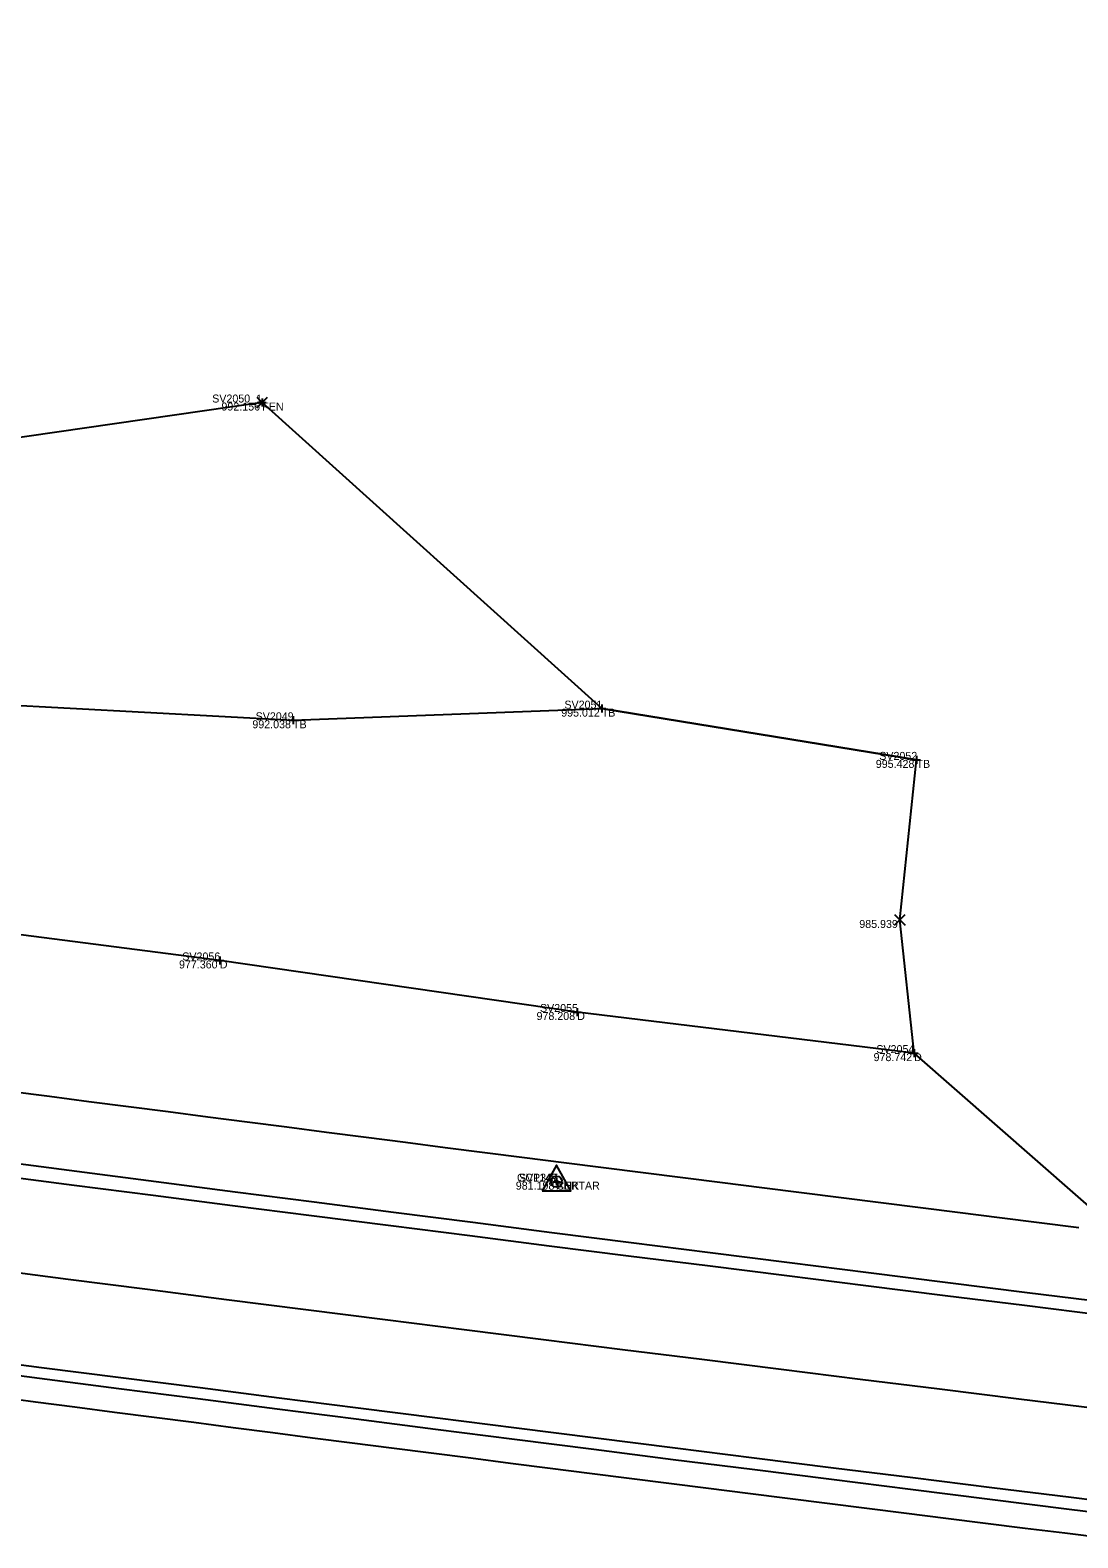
# Model space of a CAD drawing. Extents: x 2065431 to 2068157, y 709104 to 709719.
# Drawn here: x 2066723.6 to 2066854.9, y 709457.3 to 709646.1 of the extents above; entities that cross this region are included whole.
import ezdxf

# ---------------------------------------------------------------- set-up
doc = ezdxf.new("R2010")
doc.units = 0
for name, color, linetype in [('DT_X_Terrain_Boundary', 7, 'Continuous'), ('PM_X_Edge_Line', 7, 'Continuous'), ('PM_X_Lane_Line', 7, 'Continuous'), ('PV_X_EOP', 7, 'Continuous'), ('PV_X_Shoulder_Rumble_Strip', 7, 'Continuous'), ('RS_Raster1', 7, 'Continuous'), ('RW_X_CL_100_Bearings', 7, 'Continuous'), ('RW_X_Fee_WL', 7, 'Continuous'), ('SV_P_Aerial_Targets', 7, 'Continuous'), ('SV_X_Mon_Cells_Found', 7, 'Continuous'), ('SV_X_Text_Elevation', 7, 'Continuous'), ('SV_X_Text_Name', 7, 'Continuous'), ('SV_X_Top_of_Bank', 7, 'Continuous')]:
    doc.layers.add(name, color=color, linetype=linetype)

msp = doc.modelspace()

# ---------------------------------------------------------------- linework, layer by layer
at = {"layer": 'DT_X_Terrain_Boundary'}
msp.add_lwpolyline([(2066859.95, 709495.56), (2066834.34, 709517.99), (2066832.56, 709534.67), (2066834.65, 709554.72), (2066795.22, 709561.14), (2066752.69, 709599.48), (2066649.44, 709584.58), (2066543.44, 709596.37)], dxfattribs=at)
at = {"layer": 'PM_X_Edge_Line'}
for points in [[(2066719.2, 709502.76), (2066729.12, 709501.47), (2066739.04, 709500.2), (2066748.95, 709498.92), (2066758.87, 709497.66), (2066768.79, 709496.39), (2066778.71, 709495.13), (2066788.63, 709493.87), (2066798.56, 709492.62), (2066808.48, 709491.37), (2066818.4, 709490.13), (2066828.32, 709488.89), (2066838.25, 709487.65), (2066848.17, 709486.42), (2066858.09, 709485.19)], [(2066715.12, 709479.91), (2066725.04, 709478.63), (2066734.96, 709477.36), (2066744.9, 709476.09), (2066754.8, 709474.82), (2066764.72, 709473.56), (2066774.64, 709472.3), (2066784.56, 709471.04), (2066794.48, 709469.79), (2066804.4, 709468.54), (2066814.32, 709467.3), (2066824.25, 709466.06), (2066834.17, 709464.82), (2066844.09, 709463.59), (2066854.02, 709462.36), (2066863.94, 709461.13)]]:
    msp.add_lwpolyline(points, dxfattribs=at)
at = {"layer": 'PM_X_Lane_Line'}
msp.add_lwpolyline([(2066718.47, 709490.98), (2066728.39, 709489.68), (2066738.31, 709488.41), (2066748.23, 709487.15), (2066758.15, 709485.89), (2066768.07, 709484.63), (2066777.99, 709483.38), (2066787.91, 709482.13), (2066797.83, 709480.88), (2066807.76, 709479.64), (2066817.68, 709478.4), (2066827.6, 709477.16), (2066837.53, 709475.93), (2066847.45, 709474.7), (2066857.37, 709473.48)], dxfattribs=at)
at = {"layer": 'PV_X_EOP'}
for points in [[(2066721.07, 709513.24), (2066726.03, 709512.6), (2066730.98, 709511.95), (2066735.94, 709511.31), (2066740.9, 709510.67), (2066745.86, 709510.02), (2066750.82, 709509.38), (2066755.78, 709508.74), (2066760.74, 709508.1), (2066765.7, 709507.47), (2066770.65, 709506.83), (2066775.61, 709506.19), (2066780.57, 709505.56), (2066785.53, 709504.93), (2066790.49, 709504.29), (2066795.45, 709503.66), (2066800.41, 709503.03), (2066805.37, 709502.4), (2066810.33, 709501.78), (2066815.29, 709501.15), (2066820.26, 709500.52), (2066825.22, 709499.9), (2066830.18, 709499.28), (2066835.14, 709498.65), (2066840.1, 709498.03), (2066845.06, 709497.41), (2066850.02, 709496.79), (2066854.98, 709496.17)], [(2066719.31, 709474.97), (2066724.27, 709474.32), (2066729.23, 709473.68), (2066734.19, 709473.03), (2066739.15, 709472.39), (2066744.1, 709471.75), (2066749.06, 709471.1), (2066754.02, 709470.46), (2066758.98, 709469.82), (2066763.94, 709469.19), (2066768.9, 709468.55), (2066773.86, 709467.91), (2066778.82, 709467.28), (2066783.78, 709466.65), (2066788.74, 709466.01), (2066793.7, 709465.38), (2066798.66, 709464.75), (2066803.62, 709464.12), (2066808.58, 709463.49), (2066813.54, 709462.87), (2066818.5, 709462.24), (2066823.46, 709461.62), (2066828.42, 709460.99), (2066833.38, 709460.37), (2066838.34, 709459.75), (2066843.31, 709459.13), (2066848.27, 709458.51), (2066853.23, 709457.89), (2066858.19, 709457.28)]]:
    msp.add_lwpolyline(points, dxfattribs=at)
at = {"layer": 'PV_X_Shoulder_Rumble_Strip'}
for points in [[(2066719.54, 709504.5), (2066729.46, 709503.21), (2066739.38, 709501.92), (2066749.29, 709500.63), (2066759.21, 709499.35), (2066769.13, 709498.08), (2066779.05, 709496.8), (2066788.97, 709495.54), (2066798.89, 709494.27), (2066808.81, 709493.01), (2066818.73, 709491.76), (2066828.65, 709490.51), (2066838.57, 709489.26), (2066848.5, 709488.02), (2066858.42, 709486.79)], [(2066714.88, 709478.57), (2066724.8, 709477.29), (2066734.71, 709476), (2066744.63, 709474.72), (2066754.55, 709473.44), (2066764.47, 709472.17), (2066774.39, 709470.9), (2066784.31, 709469.63), (2066794.23, 709468.37), (2066804.15, 709467.11), (2066814.07, 709465.86), (2066823.99, 709464.61), (2066833.91, 709463.36), (2066843.83, 709462.12), (2066853.76, 709460.88), (2066863.68, 709459.65)]]:
    msp.add_lwpolyline(points, dxfattribs=at)
at = {"layer": 'RS_Raster1'}
for p, q in [((2066752.19, 709599.48), (2066753.19, 709599.48)), ((2066752.69, 709599.98), (2066752.69, 709598.98)), ((2066752.69, 709599.48), (2066752.69, 709599.48)), ((2066795.22, 709561.64), (2066795.22, 709560.64)), ((2066756.05, 709559.68), (2066757.05, 709559.68)), ((2066756.55, 709560.18), (2066756.55, 709559.18)), ((2066756.55, 709559.68), (2066756.55, 709559.68)), ((2066794.72, 709561.14), (2066795.72, 709561.14)), ((2066795.22, 709561.14), (2066795.22, 709561.14)), ((2066834.15, 709554.72), (2066835.15, 709554.72)), ((2066834.65, 709555.22), (2066834.65, 709554.22)), ((2066834.65, 709554.72), (2066834.65, 709554.72)), ((2066746.87, 709529.6), (2066747.87, 709529.6)), ((2066747.37, 709530.1), (2066747.37, 709529.1)), ((2066747.37, 709529.6), (2066747.37, 709529.6)), ((2066791.65, 709523.14), (2066792.65, 709523.14)), ((2066792.15, 709523.64), (2066792.15, 709522.64)), ((2066792.15, 709523.14), (2066792.15, 709523.14)), ((2066834.34, 709518.49), (2066834.34, 709517.49)), ((2066833.84, 709517.99), (2066834.84, 709517.99)), ((2066834.34, 709517.99), (2066834.34, 709517.99)), ((2066789.05, 709501.89), (2066790.05, 709501.89)), ((2066789.55, 709502.39), (2066789.55, 709501.39)), ((2066789.55, 709501.89), (2066789.55, 709501.89))]:
    msp.add_line(p, q, dxfattribs=at)
at = {"layer": 'RW_X_CL_100_Bearings'}
for p, q in [((2066752.02, 709598.81), (2066753.35, 709600.15)), ((2066752.02, 709600.15), (2066753.35, 709598.81)), ((2066831.89, 709534), (2066833.23, 709535.34)), ((2066831.89, 709535.34), (2066833.23, 709534))]:
    msp.add_line(p, q, dxfattribs=at)
at = {"layer": 'RW_X_Fee_WL'}
msp.add_lwpolyline([(2066834.34, 709517.99), (2066792.15, 709523.14), (2066747.37, 709529.6), (2066701.7, 709535.47), (2066656.28, 709541.34), (2066614.98, 709547.01), (2066577.22, 709555.89), (2066538.15, 709580.88), (2066497.57, 709596.35), (2066445.11, 709628.08), (2066445.1, 709628.08), (2066425.53, 709638.57), (2066410.9, 709640.69), (2066399.97, 709646.12), (2066394.4, 709644.52), (2066392.47, 709644.49), (2066393.15, 709634.42)], dxfattribs=at)
at = {"layer": 'SV_P_Aerial_Targets'}
msp.add_lwpolyline([(2066787.75, 709500.74), (2066791.35, 709500.74), (2066789.55, 709503.96)], close=True, dxfattribs=at)
for radius in [0.7, 0.16]:
    msp.add_circle((2066789.55, 709501.89), radius, dxfattribs=at)
at = {"layer": 'SV_X_Top_of_Bank'}
msp.add_lwpolyline([(2066625.43, 709566.82), (2066667.82, 709567.1), (2066719.28, 709561.7), (2066756.55, 709559.68), (2066795.22, 709561.14), (2066834.65, 709554.72)], dxfattribs=at)

# ---------------------------------------------------------------- texts
at = {"layer": 'SV_X_Mon_Cells_Found'}
for s, p in [('SV2050_1', (2066746.42, 709599.48)), ('SV2051', (2066790.54, 709561.14)), ('SV2049', (2066751.86, 709559.68)), ('SV2052', (2066829.98, 709554.72)), ('SV2056', (2066742.67, 709529.6)), ('SV2055', (2066787.48, 709523.14)), ('SV2054', (2066829.62, 709517.99)), ('GCP347', (2066784.6, 709501.89)), ('SV1149', (2066784.86, 709501.89))]:
    msp.add_text(s, height=1, dxfattribs=at).set_placement(p)
at = {"layer": 'SV_X_Text_Elevation'}
for s, p in [('FEN', (2066752.69, 709598.48)), ('TB', (2066756.55, 709558.68)), ('TB', (2066795.22, 709560.14)), ('TB', (2066834.65, 709553.72)), ('D', (2066747.37, 709528.6)), ('D', (2066792.15, 709522.14)), ('D', (2066834.34, 709516.99)), ('AERTAR', (2066789.55, 709500.89)), ('CHK', (2066789.55, 709500.89))]:
    msp.add_text(s, height=1, dxfattribs=at).set_placement(p)
at = {"layer": 'SV_X_Text_Name'}
for s, p in [('992.156', (2066747.58, 709598.48)), ('992.156', (2066747.58, 709598.48)), ('992.038', (2066751.45, 709558.68)), ('995.012', (2066790.14, 709560.14)), ('995.428', (2066829.55, 709553.72)), ('985.939', (2066827.48, 709533.67)), ('977.360', (2066742.26, 709528.6)), ('978.208', (2066787.05, 709522.14)), ('978.742', (2066829.27, 709516.99)), ('981.198', (2066784.45, 709500.89)), ('981.198', (2066784.45, 709500.89))]:
    msp.add_text(s, height=1, dxfattribs=at).set_placement(p)

doc.saveas('drawing.dxf')
